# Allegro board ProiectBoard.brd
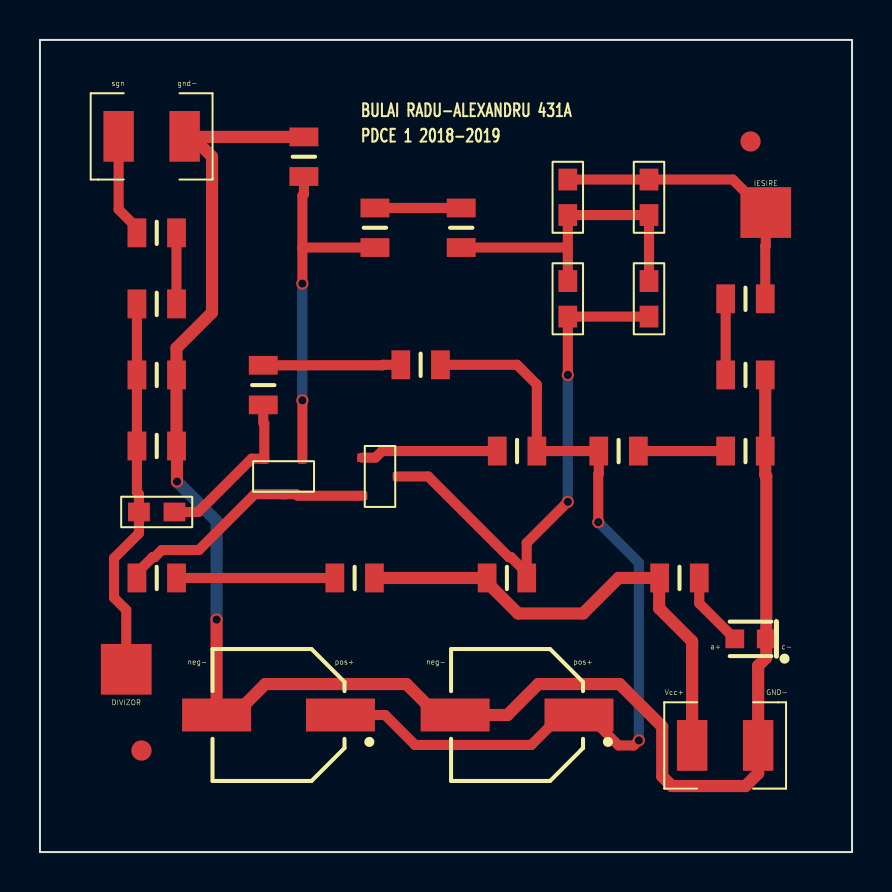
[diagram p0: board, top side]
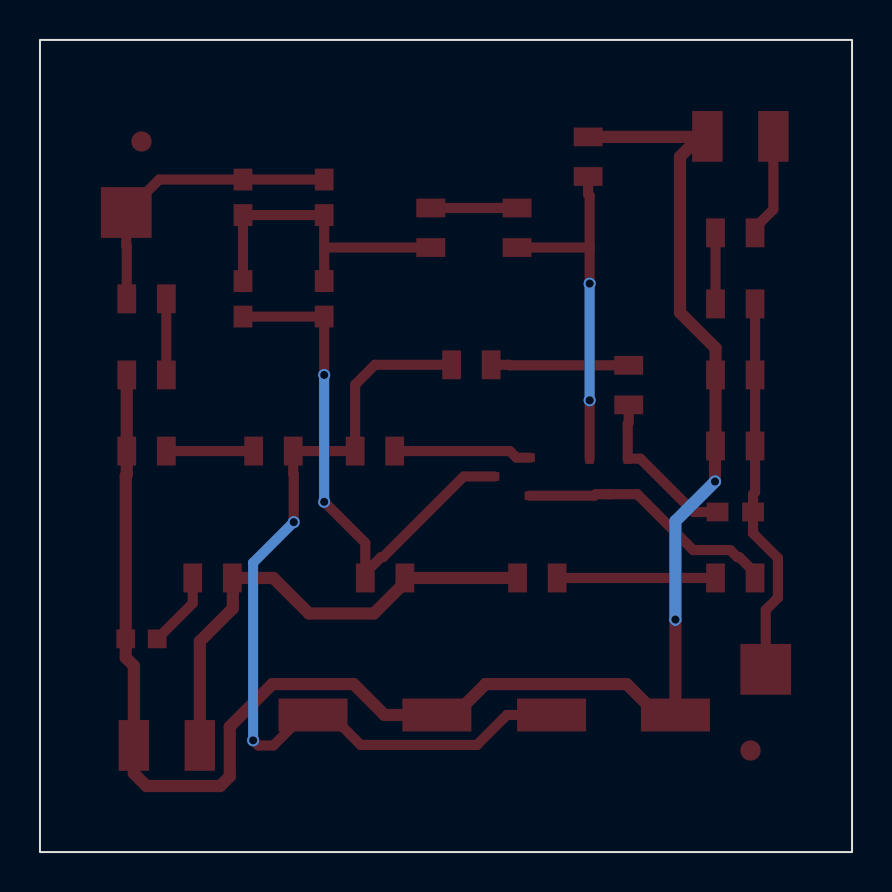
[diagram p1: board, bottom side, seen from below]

Outline 40.64 x 40.64 mm; copper layers: TOP, BOTTOM. Coordinates in mm from the lower left corner of the outline.
Outline path: rectangle 0,0 40.64,40.64

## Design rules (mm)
nets with their own width: min track width 0.508; nets N13055 N13105 N13116 N13163 N13377 N13381 N13489 N13829 N13964 N13972 N14533 N15082 N16627 N20675 N129931 N130491 N162401
nets with their own width: min track width 0.61; nets 0 VCC

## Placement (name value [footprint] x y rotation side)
C1  2.2u  [CAPC2008X126N_0805]  5.84 17.02 180 top
C2  4.7u  [CAPC2008X126N_0805]  26.42 27.69 90 top
C3  4.7u  [CAPC2008X126N_0805]  26.42 32.77 90 top
C4  4.7u  [CAPC2008X126N_0805]  30.48 27.69 90 top
C5  4.7u  [CAPC2008X126N_0805]  30.48 32.77 90 top
C6  10u  [CAPAE660X770N]  23.88 6.86 180 top
C7  10u  [CAPAE660X770N]  11.94 6.86 180 top
D1  LED  [DIOM2012X160L]  35.56 10.67 180 top
J1  POWER  [1210RF_WV_12D]  34.29 5.33 0 top
J2  INTRARE  [1210RF_WV_12D]  5.59 35.81 180 top
J3  IESIRE  [SMD_PAD_3-05_1-80]  36.32 32 180 top
J4  Divizor  [SMD_PAD_3-05_1-80]  4.32 9.14 0 top
NOREF  -  []  0 40.64 0 top
NOREF#2  Value  [unnamed#2]  5.08 5.08 0 top
NOREF#3  -  [unnamed#2]  35.56 35.56 0 top
NOREF#4  -  []  0 0 90 top
P1  4.7k  [RES2012X50N_0805]  35.31 27.69 180 top
P2  2.2k  [RES2012X50N_0805]  35.31 23.88 0 top
Q1  QBC846B  [SOT23]  12.19 18.8 270 top
Q2  QBC846B  [SOT23]  17.02 18.8 0 top
R1  1Meg  [RES2012X50N_0805]  5.84 20.32 0 top
R2  100k  [RES2012X50N_0805]  15.75 13.72 180 top
R3  100k  [RES2012X50N_0805]  5.84 13.72 180 top
R4  1k  [RES2012X50N_0805]  13.21 34.8 90 top
R5  510  [RES2012X50N_0805]  28.96 20.07 0 top
R6  510  [RES2012X50N_0805]  35.31 20.07 0 top
R7  180k  [RES2012X50N_0805]  11.18 23.37 90 top
R8  180k  [RES2012X50N_0805]  19.05 24.38 0 top
R9  100k  [RES2012X50N_0805]  16.76 31.24 270 top
R10  180k  [RES2012X50N_0805]  21.08 31.24 90 top
R11  1  [RES2012X50N_0805]  23.88 20.07 0 top
R12  15k  [RES2012X50N_0805]  23.37 13.72 0 top
R13  390k  [RES2012X50N_0805]  5.84 30.99 0 top
R14  390k  [RES2012X50N_0805]  5.84 27.43 180 top
R15  22k  [RES2012X50N_0805]  5.84 23.88 180 top
R16  1k  [RES2012X50N_0805]  32 13.72 0 top

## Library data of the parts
C1-C5 = C
C6 C7 = CAP POL_0
D1 = LED_0
J1 = CON2_0
J2 = CON2
J3 J4 = CON1
P1 P2 R1-R15 = R
Q1 Q2 = 2N2221
R16 = RESISTOR

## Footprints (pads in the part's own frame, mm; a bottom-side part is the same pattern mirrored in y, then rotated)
1210RF_WV_12D
  rect 1.524x2.54 smd: 1(-1.651,0) 2(1.651,0)
CAPAE660X770N
  rect 3.454x1.651 smd: 1(-3.099,0) 2(3.099,0)
CAPC2008X126N_0805
  rect 1.092x0.94 smd: 1(-0.889,0) 2(0.889,0)
DIOM2012X160L
  rect 0.94x0.94 smd: A(0.787,0) C(-0.787,0)
RES2012X50N_0805
  rect 0.94x1.448 smd: 1(-0.991,0) 2(0.991,0)
SMD_PAD_3-05_1-80
  rect 2.54x2.54 smd: 1(0,0)
SOT23
  rect 0.508x0.432 smd: 1(-0.889,0.94) 2(-0.889,-0.965) 3(0.889,0)
unnamed#2
  round 1.016 smd: 1(0,0)

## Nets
VCC: J1.1 R2.1 R12.1 R16.1
0: C6.2 C7.2 D1.C(CATHODE) J1.2 J2.1 P2.2 R1.2 R4.2 R6.2 R15.1
N13055: Q1.3(COLLECTOR) Q2.2(BASE) R3.2
N13105: C1.1 Q1.2(BASE) R7.1
N13116: C1.2 J4.1 R1.1 R14.2 R15.2
N13163: Q1.1(EMITTER) R4.1 R9.2
N13377: R7.2 R8.1
N13381: C6.1 C7.1 R5.1 R8.2 R11.2
N13489: R9.1 R10.2
N13829: C2.1 C4.1 Q2.3(COLLECTOR) R12.2
N13964: C3.2 C5.2 J3.1 P1.1
N13972: C2.2 C3.1 C4.2 C5.1 R10.1
N14533: P1.2 P2.1
N15082: D1.A(ANODE) R16.2
N16627: J2.2 R13.1
N20675: R5.2 R6.1
N129931: R2.2 R3.1
N130491: Q2.1(EMITTER) R11.1
N162401: R13.2 R14.1

Pads without a net: NOREF#2 1; NOREF#3 1

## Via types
v1: diameter 0.61, hole 0.406, TOP to BOTTOM, 8 vias

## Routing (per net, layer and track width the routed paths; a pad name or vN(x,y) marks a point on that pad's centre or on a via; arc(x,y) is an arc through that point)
VCC: length 25
  TOP w0.61: 32.64,5.33 32.64,10.54 30.99,12.19 30.99,13.69 R16.1 28.96,13.72 27.18,11.94 23.93,11.94 22.38,13.49 R12.1 R2.1
0: length 89.9
  TOP w0.61: J2.1 7.26,35.79 7.62,35.79 ; 7.62,35.79 8.61,34.8 8.61,27 6.83,25.22 R15.1 R1.2 6.86,20.29 v1(6.86,18.54) ; 7.62,35.79 R4.2 ; P2.2 R6.2 36.3,18.87 36.35,18.82 D1.C 36.35,9.73 35.94,9.32 J1.2 35.94,3.94 35.31,3.3 31.62,3.3 31.14,3.78 31.14,6.27 29.01,8.41 24.94,8.41 23.39,6.86 C6.2 19.89,6.86 18.34,8.41 11.28,8.41 9.73,6.86 C7.2 v1(8.84,11.63)
  BOTTOM w0.61: v1(6.86,18.54) 8.84,16.56 v1(8.84,11.63)
N13055: length 13.2
  TOP w0.508: Q2.2 12.9,17.83 12.83,17.91 Q1.3 10.74,17.91 7.95,15.11 6.1,15.11 5.74,14.76 5.64,14.76 4.85,13.97 R3.2
N13105: length 8.3
  TOP w0.508: C1.1 7.92,17.02 10.59,19.68 Q1.2 11.23,21.44 11.18,21.49 R7.1
N13116: length 19.1
  TOP w0.508: R14.2 R15.2 R1.1 4.85,18.01 4.95,17.91 C1.2 4.95,15.95 3.71,14.71 3.71,12.73 4.32,12.12 J4.1
N13163: length 17.8
  TOP w0.508: v1(13.13,28.45) 13.13,30.23 ; 13.13,30.23 13.16,30.25 R9.2 ; 13.13,30.23 13.13,32.84 13.21,32.92 R4.1 ; Q1.1 v1(13.13,22.61)
  BOTTOM w0.508: v1(13.13,22.61) v1(13.13,28.45)
N13377: length 6.9
  TOP w0.508: R8.1 17.17,24.38 17.14,24.36 R7.2
N13381: length 43.9
  TOP w0.508: v1(29.97,5.59) 29.72,5.33 28.96,5.33 27.43,6.86 C6.1 26.09,6.86 24.59,5.36 18.77,5.36 17.27,6.86 C7.1 ; R8.2 23.88,24.38 24.87,23.39 R11.2 R5.1 27.97,18.92 27.94,18.9 v1(27.94,16.51)
  BOTTOM w0.508: v1(27.94,16.51) 29.97,14.48 v1(29.97,5.59)
N13489: length 4.3
  TOP w0.508: R9.1 R10.2
N13829: length 26.4
  TOP w0.508: R12.2 24.36,13.97 ; 24.36,13.97 23.57,14.76 23.47,14.76 19.43,18.8 Q2.3 ; 24.36,13.97 24.36,15.47 v1(26.42,17.53) ; v1(26.42,23.88) C2.1 C4.1
  BOTTOM w0.508: v1(26.42,17.53) v1(26.42,23.88)
N13964: length 14.9
  TOP w0.508: C3.2 C5.2 34.67,33.66 J3.1 36.32,30.33 36.3,30.3 P1.1
N13972: length 16
  TOP w0.508: C2.2 26.42,30.23 ; 26.42,30.23 C3.1 C5.1 C4.2 ; 26.42,30.23 26.39,30.25 R10.1
N14533: length 3.8
  TOP w0.508: P2.1 P1.2
N15082: length 3.8
  TOP w0.508: R16.2 32.99,12.45 D1.A
N16627: length 5.2
  TOP w0.508: 3.94,35.81 3.94,32.16 4.85,31.24 R13.1
N20675: length 4.4
  TOP w0.508: R6.1 R5.2
N129931: length 7.9
  TOP w0.508: R3.1 R2.2
N130491: length 6.9
  TOP w0.508: Q2.1 16.79,19.74 17.12,20.07 R11.1
N162401: length 3.6
  TOP w0.508: R13.2 R14.1

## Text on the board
Ref Des/Silkscreen Top: sgn | gnd- | neg- | pos+ | Vcc+ | a+ | GND- | c- | BULAI RADU-ALEXANDRU 431A | PDCE 1 2018-2019
XSECTION_CHART: *  SURFACE - AIR 0 MIL | L1: TOP CONDUCTOR - COPPER 1 MIL | *  DIELECTRIC - FR-4 58 MIL | L2: BOTTOM CONDUCTOR - COPPER 1 MIL | DESIGN CROSS SECTION CHART | ___________________________ | TOTAL THICKNESS 60 MIL | 1-2
DISPLAY_TOP: FIGURE | SIZE | 16.0 | DRILL CHART: TOP to BOTTOM | ALL UNITS ARE IN MILS | PLATED | QTY | 8
